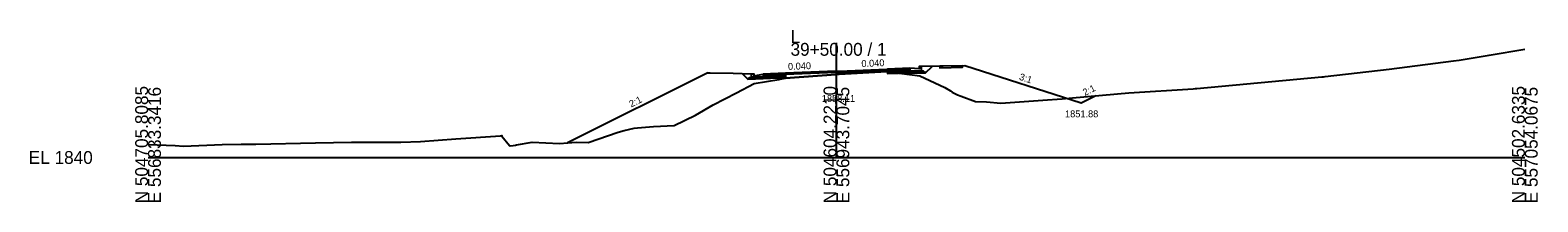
# Model space of a CAD drawing. Extents: x -26 to 4603, y -10 to 4703.
# Drawn here: x 974.3 to 1302.8, y 4620.3 to 4657.8 of the extents above; entities that cross this region are included whole.
import ezdxf

# ---------------------------------------------------------------- set-up
doc = ezdxf.new("R2010")
doc.units = 0
for name, color, linetype in [('Default', 7, 'Continuous'), ('Exist Cross Section Cell', 7, 'Continuous'), ('Exist XS Ground Line', 7, 'Continuous'), ('Prop CMT Pvmt Course 1', 7, 'Continuous'), ('Prop CMT Pvmt Course 2', 7, 'Continuous'), ('Prop CMT Pvmt Course 3', 7, 'Continuous'), ('Prop CMT Pvmt Milling', 7, 'Continuous'), ('Prop CMT Shear Line', 7, 'Continuous'), ('Prop CMT Shld Paved Course 2', 7, 'Continuous'), ('Prop CMT Shld Paved Course 3', 7, 'Continuous'), ('Prop CMT Subgrade Earthwork', 7, 'Continuous'), ('Prop Conc 4in Sidewalk', 7, 'Continuous'), ('Prop Conc Curb and Gutter', 7, 'Continuous'), ('Prop XS Ditch Slope Text', 7, 'Continuous'), ('Prop XS Finish Grade', 7, 'Continuous'), ('Prop XS Label Text', 7, 'Continuous'), ('Prop XS SS Elevation Text', 7, 'Continuous'), ('Scratch_Level_9', 7, 'Continuous')]:
    doc.layers.add(name, color=color, linetype=linetype)

msp = doc.modelspace()

# ---------------------------------------------------------------- linework, layer by layer
at = {"layer": 'Exist Cross Section Cell'}
for p, q in [((1150, 4630), (1150, 4655)), ((1000, 4630), (1150, 4630)), ((1150, 4630), (1300, 4630))]:
    msp.add_line(p, q, dxfattribs=at)
at = {"layer": 'Exist XS Ground Line'}
msp.add_lwpolyline([(1000, 4632.8), (1005.94, 4632.62), (1007.73, 4632.46), (1016.14, 4632.83), (1020.29, 4632.88), (1023.48, 4632.88), (1036.47, 4633.18), (1044.3, 4633.36), (1055.11, 4633.34), (1059.4, 4633.48), (1067.05, 4634.05), (1076.83, 4634.75), (1077.06, 4634.78), (1077.12, 4634.67), (1078.75, 4632.59), (1078.87, 4632.51), (1079.53, 4632.62), (1080.03, 4632.72), (1080.27, 4632.78), (1083.67, 4633.35), (1089.63, 4633.07), (1093.32, 4633.31), (1095.87, 4633.28), (1102.45, 4635.54), (1103.75, 4635.91), (1105.93, 4636.4), (1106.65, 4636.48), (1110.12, 4636.77), (1114.66, 4636.98), (1119.3, 4639.24), (1123.15, 4641.48), (1128.25, 4644.1), (1132.06, 4646.16), (1137.48, 4647.05), (1137.63, 4647.06), (1138.93, 4647.3), (1149.85, 4648.1), (1150.57, 4648.15), (1161, 4648.73), (1161.16, 4648.73), (1161.42, 4648.71), (1168.15, 4647.79), (1173.6, 4645.26), (1174.88, 4644.53), (1175.24, 4644.26), (1176.35, 4643.65), (1177.2, 4643.41), (1180.33, 4642.24), (1182.71, 4642.12), (1185.8, 4641.88), (1196, 4642.6), (1198.13, 4642.7), (1199.19, 4642.77), (1201.43, 4643.05), (1213.68, 4644.11), (1227.73, 4644.98), (1228.18, 4645.02), (1228.51, 4645.06), (1255.8, 4647.57), (1256.14, 4647.61), (1256.52, 4647.65), (1270.41, 4649.24), (1284.46, 4651.07), (1285.69, 4651.26), (1292.2, 4652.34), (1300, 4653.61)], dxfattribs=at)
at = {"layer": 'Prop CMT Pvmt Course 1'}
for points in [[(1149.85, 4648.82), (1138.93, 4648.38), (1138.93, 4648.38), (1138.93, 4647.3), (1138.93, 4647.3), (1138.93, 4647.3), (1149.85, 4648.1), (1149.85, 4648.1), (1150, 4648.11), (1150, 4648.11), (1150, 4648.83), (1149.85, 4648.82), (1149.85, 4648.82)], [(1161, 4649.27), (1161.16, 4649.27), (1161.16, 4648.73), (1161.16, 4648.73), (1161, 4648.73), (1161, 4648.73), (1150.57, 4648.15), (1150.57, 4648.15), (1150.57, 4648.15), (1150, 4648.11), (1150, 4648.11), (1150, 4648.83), (1150.57, 4648.85), (1150.57, 4648.85), (1150.57, 4648.85), (1161, 4649.27), (1161, 4649.27)], [(1166, 4649.47), (1161.16, 4649.27), (1161.16, 4649.02), (1161.16, 4649.02), (1166, 4649.22), (1166, 4649.22), (1166, 4649.22), (1166, 4649.47), (1166, 4649.47)], [(1138.93, 4648.38), (1134, 4648.19), (1134, 4647.94), (1134, 4647.94), (1138.93, 4648.13), (1138.93, 4648.13), (1138.93, 4648.13), (1138.93, 4648.38), (1138.93, 4648.38)]]:
    msp.add_lwpolyline(points, dxfattribs=at)
at = {"layer": 'Prop CMT Pvmt Course 2'}
for points in [[(1166, 4649.22), (1161.16, 4649.02), (1161.16, 4648.69), (1161.16, 4648.69), (1166, 4648.88), (1166, 4648.88), (1166, 4648.88), (1166, 4649.22), (1166, 4649.22)], [(1138.93, 4648.13), (1134, 4647.94), (1134, 4647.6), (1134, 4647.6), (1138.93, 4647.8), (1138.93, 4647.8), (1138.93, 4647.8), (1138.93, 4648.13), (1138.93, 4648.13)]]:
    msp.add_lwpolyline(points, dxfattribs=at)
at = {"layer": 'Prop CMT Pvmt Course 3'}
for points in [[(1166, 4648.88), (1161.16, 4648.69), (1161.16, 4648.31), (1161.16, 4648.31), (1166, 4648.51), (1166, 4648.51), (1166, 4648.51), (1166, 4648.88), (1166, 4648.88)], [(1166, 4648.88), (1166, 4648.5), (1169.38, 4648.44), (1169, 4648.82), (1166, 4648.88)], [(1138.93, 4647.8), (1134, 4647.6), (1134, 4647.23), (1134, 4647.23), (1138.93, 4647.42), (1138.93, 4647.42), (1138.93, 4647.42), (1138.93, 4647.8), (1138.93, 4647.8)]]:
    msp.add_lwpolyline(points, dxfattribs=at)
at = {"layer": 'Prop CMT Pvmt Milling'}
for points in [[(1150, 4648.11), (1149.85, 4648.1), (1149.85, 4648.1), (1138.93, 4647.3), (1138.93, 4647.3)], [(1161.16, 4648.73), (1161, 4648.73), (1161, 4648.73), (1150.57, 4648.15), (1150.57, 4648.15), (1150.57, 4648.15), (1150, 4648.11)]]:
    msp.add_lwpolyline(points, dxfattribs=at)
at = {"layer": 'Prop CMT Shld Paved Course 2'}
for points in [[(1161, 4649.02), (1161.16, 4649.02), (1161.16, 4648.69), (1161.16, 4648.69), (1161, 4648.68), (1161, 4648.68), (1158.16, 4648.57), (1158.16, 4648.57), (1158.16, 4648.57), (1150.57, 4648.15), (1150.57, 4648.15), (1150, 4648.11), (1150, 4648.11), (1150, 4648.58), (1150.57, 4648.6), (1150.57, 4648.6), (1150.57, 4648.6), (1161, 4649.02), (1161, 4649.02)], [(1149.85, 4648.57), (1138.93, 4648.13), (1138.93, 4648.13), (1138.93, 4647.3), (1138.93, 4647.3), (1138.93, 4647.3), (1149.85, 4648.1), (1149.85, 4648.1), (1150, 4648.11), (1150, 4648.11), (1150, 4648.58), (1149.85, 4648.57), (1149.85, 4648.57)]]:
    msp.add_lwpolyline(points, dxfattribs=at)
at = {"layer": 'Prop CMT Shld Paved Course 3'}
msp.add_lwpolyline([(1131, 4647.48), (1134, 4647.6), (1134, 4647.23), (1134, 4647.23), (1130.7, 4647.1), (1130.7, 4647.1), (1130.7, 4647.1), (1131, 4647.48), (1131, 4647.48)], dxfattribs=at)
at = {"layer": 'Prop CMT Subgrade Earthwork'}
for points in [[(1166, 4648.5), (1169.38, 4648.44), (1170.84, 4649.89)], [(1129.47, 4648.33), (1130.7, 4647.1), (1130.7, 4647.1)], [(1130.7, 4647.1), (1138.93, 4647.42), (1138.93, 4647.42)], [(1169.36, 4648.64), (1169.36, 4648.64), (1161.16, 4648.31)]]:
    msp.add_lwpolyline(points, dxfattribs=at)
at = {"layer": 'Prop Conc 4in Sidewalk'}
msp.add_lwpolyline([(1172.5, 4649.92), (1172.5, 4649.59), (1177.5, 4649.69), (1177.5, 4650.02), (1172.5, 4649.92)], dxfattribs=at)
at = {"layer": 'Prop Conc Curb and Gutter'}
for points in [[(1168, 4649.34), (1166, 4649.46), (1166, 4648.88), (1166, 4648.88), (1168.5, 4648.83), (1168.5, 4648.83), (1168.5, 4648.83), (1168.5, 4649.84), (1168, 4649.84), (1168, 4649.84), (1168, 4649.34), (1168, 4649.34), (1168, 4649.34)], [(1132, 4647.79), (1134, 4648.19), (1134, 4647.6), (1134, 4647.6), (1131.5, 4647.5), (1131.5, 4647.5), (1131.5, 4647.5), (1131.5, 4648.29), (1131.5, 4648.29), (1132, 4648.29), (1132, 4647.79), (1132, 4647.79), (1132, 4647.79)]]:
    msp.add_lwpolyline(points, dxfattribs=at)
at = {"layer": 'Prop XS Finish Grade'}
msp.add_line((1122.5, 4648.47), (1127.5, 4648.37), dxfattribs=at)
for points in [[(1203.31, 4641.88), (1178, 4650.03), (1178, 4650.03), (1168.5, 4649.84), (1168.5, 4649.84)], [(1122, 4648.48), (1091.42, 4633.18)], [(1122, 4648.48), (1122.5, 4648.47), (1122.5, 4648.47)], [(1127.5, 4648.37), (1131.5, 4648.29), (1131.5, 4648.29)], [(1206.54, 4643.49), (1203.31, 4641.88), (1203.31, 4641.88)]]:
    msp.add_lwpolyline(points, dxfattribs=at)
at = {"layer": 'Scratch_Level_9'}
msp.add_lwpolyline([(1134, 4648.19), (1134, 4647.94)], dxfattribs=at)

# ---------------------------------------------------------------- texts
at = {"layer": 'Default'}
msp.add_text('-', height=0.0001, dxfattribs=at).set_placement((1000, 4630))
at = {"layer": 'Exist Cross Section Cell'}
for s, p in [('L', (1140, 4655)), ('39+50.00 / 1', (1140, 4652.2)), ('EL 1840', (974, 4628.6))]:
    msp.add_text(s, height=2.8, dxfattribs=at).set_placement(p)
for s, p in [('N 504705.8085', (1000, 4620)), ('N 504604.2210', (1150, 4620)), ('N 504502.6335', (1300, 4620)), ('E 556833.3416', (1002.8, 4620)), ('E 556943.7045', (1152.8, 4620)), ('E 557054.0675', (1302.8, 4620))]:
    msp.add_text(s, height=2.8, rotation=90, dxfattribs=at).set_placement(p)
at = {"layer": 'Prop CMT Shear Line'}
for p in [(1150, 4648.82), (1166, 4649.46), (1168, 4649.34), (1172.5, 4649.92), (1177.5, 4650.02), (1178, 4650.03), (1122, 4648.47), (1122.5, 4648.46), (1127.5, 4648.36), (1132, 4647.78), (1134, 4648.18), (1134, 4648.18), (1206.54, 4643.49), (1203.31, 4641.88), (1091.41, 4633.18)]:
    msp.add_text('X', height=0.0025, dxfattribs=at).set_placement(p)
at = {"layer": 'Prop XS Ditch Slope Text'}
msp.add_text('1851.88', height=1.5, dxfattribs=at).set_placement((1199.81, 4638.77))
at = {"layer": 'Prop XS Label Text'}
for s, rotation, p in [('0.040', 2.2906, (1139.47, 4649.1)), ('0.040', 2.2906, (1155.47, 4649.74)), ('3:1', 342.1375, (1189.7, 4647)), ('2:1', 26.5651, (1204.12, 4643.4)), ('2:1', 26.5651, (1105.29, 4640.9))]:
    msp.add_text(s, height=1.5, rotation=rotation, dxfattribs=at).set_placement(p)
at = {"layer": 'Prop XS SS Elevation Text'}
msp.add_text('1858.11', height=1.5, dxfattribs=at).set_placement((1146.82, 4642.14))

doc.saveas('drawing.dxf')
